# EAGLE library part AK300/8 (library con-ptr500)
CONNECTOR
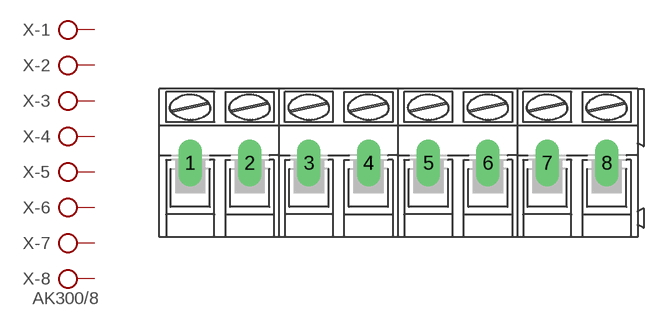
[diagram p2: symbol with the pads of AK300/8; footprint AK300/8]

Designator prefix X; gates -1=KL -2=KL -3=KL -4=KL -5=KL -6=KL -7=KL -8=KLV

## AK300/8 (OC_FARNELL: unknown; OC_NEWARK: unknown)  [AK300/8]
1  -1:KL  pas
2  -2:KL  pas
3  -3:KL  pas
4  -4:KL  pas
5  -5:KL  pas
6  -6:KL  pas
7  -7:KL  pas
8  -8:KL  pas

## Footprint AK300/8 (pad centres in mm)
CONNECTOR
drill 1.321 long: 1 -17.501,0; 2 -12.497,0; 3 -7.518,0; 4 -2.515,0; 5 2.515,0; 6 7.518,0; 7 12.497,0; 8 17.501,0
